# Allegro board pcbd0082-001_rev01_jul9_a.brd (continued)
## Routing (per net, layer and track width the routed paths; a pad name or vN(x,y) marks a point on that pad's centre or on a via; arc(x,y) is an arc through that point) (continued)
DDR0_32A_A12: length 67.2
  TOP w0.147: V3_A-A12.1 85.01,29.64 R218.1
  TOP w0.234: v2(66.9,44.28) U1.Y8
  03_SIG w0.121: V1_A-A12.1 84.62,51.73 84.62,40.96 V2_A-A12.1 84.62,40.17 84.62,29.41 V3_A-A12.1
  08_SIG w0.121: V1_A-A12.1 85.01,51.88 85.41,51.49 85.41,50.11
  08_SIG w0.189: v2(66.9,44.28) 68.4,42.78 74.12,42.78 74.37,43.04 75.09,43.04 75.1,43.02 76.52,43.02 76.54,43.04 78.33,43.04 78.75,42.62 78.75,42.37 78.93,42.19 87.73,42.19 87.75,42.2 88.75,42.2 88.94,42.39 88.94,49.27 88.73,49.48 86.83,49.48 86.68,49.33 86.68,47.67 86.5,47.5 85.64,47.5 85.41,47.73 85.41,50.11
  BOTTOM w0.147: U17.N7 V1_A-A12.1 ; U18.N7 V2_A-A12.1 ; U19.N7 V3_A-A12.1
DDR0_32A_A13: length 67.3
  TOP w0.147: V3_A-A13.1 87.41,32.65 R219.1
  TOP w0.234: v2(66.9,49.28) U1.AE8
  07_SIG w0.121: V3_A-A13.1 87.87,33.46 87.87,44.12 V2_A-A13.1 87.81,44.96 87.81,55.73 V1_A-A13.1
  07_SIG w0.189: V1_A-A13.1 87.85,56.56 87.85,60.42 87.84,60.43 87.84,60.68 87.66,60.86 65.95,60.86 65.75,60.65 65.75,59.23 66,58.98 67.11,58.98 67.32,58.77 67.32,57.14 67.33,57.13 67.33,56.47 67.34,56.46 67.34,56.1 67.33,56.1 67.33,56.06 66.4,55.13 66.4,49.78 v2(66.9,49.28)
  BOTTOM w0.147: U18.T3 V2_A-A13.1 ; U17.T3 V1_A-A13.1 ; U19.T3 V3_A-A13.1
DDR0_32A_A14: length 67.3
  TOP w0.147: V3_A-A14.1 87.41,29.37 R220.1
  TOP w0.234: v8(67.9,38.28) U1.R7
  04_SIG w0.121: V3_A-A14.1 87.87,29.46 87.87,40.12 V2_A-A14.1 87.87,41.03 87.87,51.67 V1_A-A14.1
  08_SIG w0.189: v8(67.9,38.28) 68.39,37.8 70.14,37.8 70.63,38.28 74.81,38.28 74.98,38.46 74.98,41.55 75.17,41.73 75.17,41.75 75.35,41.93 77.23,41.93 77.51,41.65 77.51,41.25 77.71,41.04 87.72,41.04 87.75,41.02 89.44,41.02 89.45,41.03 89.74,41.03 89.75,41.04 89.93,41.04 90.11,41.22 90.11,41.69 90.13,41.71 90.13,51.2 90.11,51.22 90.11,51.95 89.93,52.13 V1_A-A14.1
  BOTTOM w0.147: U17.T7 V1_A-A14.1 ; U18.T7 V2_A-A14.1 ; U19.T7 V3_A-A14.1
DDR0_32A_BA0: length 68.5
  TOP w0.147: R224.1 83.43,34.6 V3_A-BA0.1
  TOP w0.234: v8(65.9,41.28) U1.U9
  03_SIG w0.121: 84.61,57.97 84.61,57.32 V1_A-BA0.1
  03_SIG w0.189: 84.61,57.97 84.61,60.18 84.61,60.19 84.61,60.2 83.9,60.91 77,60.91 77,60.9 70,60.9 69.99,60.89 69.91,60.89 66.95,57.93 66.95,57.36 66.4,56.81 66.4,50.05 66.13,49.78 65.75,49.78 65.4,49.43 65.4,41.78 v8(65.9,41.28)
  07_SIG w0.121: V3_A-BA0.1 83.82,34.21 83.82,44.97 V2_A-BA0.1 83.82,45.76 83.82,56.42 84.21,56.82 V1_A-BA0.1
  BOTTOM w0.147: U17.M2 V1_A-BA0.1 ; U18.M2 V2_A-BA0.1 ; U19.M2 V3_A-BA0.1
DDR0_32A_BA1: length 68.5
  TOP w0.147: V3_A-BA1.1 84.19,29.04 R223.1
  TOP w0.234: v8(68.9,46.28) U1.AB6
  03_SIG w0.121: V1_A-BA1.1 85.41,50.93 85.41,40.17 V2_A-BA1.1 85.41,39.37 85.41,28.61 V3_A-BA1.1
  08_SIG w0.189: V1_A-BA1.1 84.59,51.75 84.59,51.94 84.58,51.95 84.58,52.3 84.84,52.55 84.84,52.55 86.03,53.74 87.7,53.74 87.75,53.79 88.58,53.79 88.86,54.07 88.86,54.33 88.68,54.51 85.69,54.51 85.56,54.38 85.56,53.85 85.33,53.62 85.08,53.62 84.9,53.79 84.9,54 84.75,54.15 84.34,54.15 84.16,53.97 84.16,52.78 83.96,52.58 83.71,52.58 83.5,52.78 83.5,53.97 83.32,54.15 82.94,54.15 82.79,54 82.79,53.47 82.66,53.34 82.33,53.34 82.18,53.49 82.18,53.97 82,54.15 81.67,54.15 81.52,54 81.52,53.54 81.34,53.36 78.73,53.36 78.15,52.78 77.78,52.78 77.2,53.36 77.2,53.36 75.17,53.36 74.72,52.92 74.72,49.84 74.73,49.84 74.73,49.42 74.74,49.41 74.74,48.95 74.66,48.87 74.66,47.97 74.47,47.78 72.58,47.78 72.4,47.61 72.4,46.99 72.13,46.72 71.63,46.72 71.36,46.99 71.36,47.58 71.16,47.78 70.61,47.78 70.4,47.58 70.4,46.86 70.3,46.76 69.09,46.76 68.9,46.57 v8(68.9,46.28)
  BOTTOM w0.147: U19.N8 V3_A-BA1.1 ; U17.N8 V1_A-BA1.1 ; U18.N8 V2_A-BA1.1
DDR0_32A_BA2: length 67.9
  TOP w0.147: R222.1 84.21,32.34 V3_A-BA2.1
  TOP w0.234: v8(68.9,48.28) U1.AD6
  04_SIG w0.121: V1_A-BA2.1 83.82,55.73 83.82,44.96 V2_A-BA2.1 83.82,44.17 83.82,33.41 V3_A-BA2.1
  07_SIG w0.121: V1_A-BA2.1 84.21,56.37 84.61,56.76 84.61,58.02
  07_SIG w0.189: v8(68.9,48.28) 68.9,47.96 69.09,47.78 69.78,47.78 69.85,47.85 70.08,47.85 70.34,48.1 70.34,49.46 69.96,49.84 69.96,50.73 70.34,51.1 70.34,51.46 69.96,51.84 69.96,52.73 70.34,53.1 70.34,54.46 69.33,55.47 69.33,55.9 70.04,56.62 70.04,58.04 69.91,58.17 69.58,58.17 69.45,58.04 69.45,56.84 69.33,56.72 69.02,56.72 68.85,56.89 68.85,58.65 68.84,58.67 68.84,59.24 68.85,59.25 68.85,59.46 69.04,59.65 86.15,59.65 86.34,59.47 86.34,59.2 86.09,58.95 84.86,58.95 84.61,58.7 84.61,58.02
  BOTTOM w0.147: U19.M3 V3_A-BA2.1 ; U18.M3 V2_A-BA2.1 ; U17.M3 V1_A-BA2.1
DDR0_32A_CAS_L: length 67.1
  TOP w0.147: V3_A-CAS.1 82.61,32.52 R226.1
  TOP w0.234: v2(65.9,46.28) U1.AB9
  03_SIG w0.121: 83.79,57.91 83.79,57.11 83.81,57.09 83.81,56.76 83.56,56.52 83.01,56.52 V1_A-CAS.1
  03_SIG w0.189: v2(65.9,46.28) 66.4,46.78 66.4,49.43 66.75,49.78 67.02,49.78 67.33,50.1 67.34,50.1 67.34,53.46 67.33,53.47 67.33,53.58 66.79,54.13 66.79,55.55 67.34,56.1 67.34,56.16 67.34,57.77 70.07,60.5 70.15,60.5 70.16,60.51 82.35,60.51 82.54,60.32 82.54,58.32 82.71,58.14 83.02,58.14 83.2,58.32 83.2,60.37 83.32,60.5 83.75,60.5 84.21,60.04 84.21,58.41 83.79,57.99 83.79,57.91
  04_SIG w0.121: V1_A-CAS.1 82.22,55.73 82.22,44.96 V2_A-CAS.1 82.22,44.17 82.22,33.41 V3_A-CAS.1
  BOTTOM w0.147: U19.K3 V3_A-CAS.1 ; U18.K3 V2_A-CAS.1 ; U17.K3 V1_A-CAS.1
DDR0_32A_CB0: length 19
  TOP w0.132: v8(72.9,41.28) U1.U2
  04_SIG w0.121: V_A-CB0.1 79.01,34.21 79.01,35.31 79.18,35.48 81.17,35.48 81.29,35.61 81.29,37.82 81.11,38 74.79,38 74.66,38.12 74.66,40.33 74.46,40.54 73.14,40.54 72.9,40.78 v8(72.9,41.28)
  BOTTOM w0.147: U19.F2 V_A-CB0.1
DDR0_32A_CB1: length 19
  TOP w0.132: v8(70.9,39.28) U1.T4
  04_SIG w0.121: V_A-CB1.1 80.21,30.47 80.05,30.63 73.85,30.63 72.58,31.9 72.58,35.3 71.62,36.27 71.62,38.5 70.9,39.22 v8(70.9,39.28)
  BOTTOM w0.147: U19.H7 V_A-CB1.1
DDR0_32A_CB2: length 19.1
  TOP w0.132: v2(70.9,41.28) U1.U4
  04_SIG w0.121: V_A-CB2.1 78.21,33.41 78.21,35.58 78.52,35.89 78.9,35.89 79.9,36.88 79.9,37.21 79.49,37.62 74.54,37.62 74.31,37.84 74.31,39.91 74.19,40.03 71.11,40.03 70.9,40.24 v2(70.9,41.28)
  BOTTOM w0.147: U19.E3 V_A-CB2.1
DDR0_32A_CB3: length 19.5
  TOP w0.132: v8(69.9,39.28) U1.T5
  04_SIG w0.121: v8(69.9,39.28) 71.31,37.87 71.31,36.01 72.3,35.02 72.3,31.72 73.7,30.33 78.7,30.33 79.81,29.21 79.81,28.61 V_A-CB3.1
  BOTTOM w0.147: U19.H8 V_A-CB3.1
DDR0_32A_CB4: length 19.1
  TOP w0.132: v8(68.9,39.28) U1.T6
  04_SIG w0.121: V_A-CB4.1 78.21,28.61 78.21,29.19 77.69,29.72 73.24,29.72 69.46,33.5 69.46,38.89 69.06,39.28 v8(68.9,39.28)
  BOTTOM w0.147: U19.F8 V_A-CB4.1
DDR0_32A_CB5: length 19.1
  TOP w0.132: v8(69.9,38.28) U1.R5
  04_SIG w0.121: V_A-CB5.1 78.61,29.83 78.42,30.02 73.49,30.02 70.48,33.03 70.48,33.66 70.6,33.78 71.39,33.78 71.51,33.9 71.51,34.78 71.39,34.9 70.6,34.9 70.48,35.02 70.48,38.11 70.31,38.28 v8(69.9,38.28)
  BOTTOM w0.147: U19.F7 V_A-CB5.1
DDR0_32A_CB6: length 19.3
  TOP w0.132: v2(73.9,41.28) U1.U1
  04_SIG w0.121: v2(73.9,41.28) 74.37,41.28 74.92,40.74 74.92,38.61 75.12,38.4 81.52,38.4 81.7,38.23 81.7,35.29 81.37,34.96 81.37,34.34 81.24,34.21 80.78,34.21 80.66,34.34 80.66,34.97 80.56,35.08 79.97,35.08 79.81,34.92 79.81,34.21 V_A-CB6.1
  BOTTOM w0.147: U19.G2 V_A-CB6.1
DDR0_32A_CB7: length 19.1
  TOP w0.132: v8(71.9,39.28) U1.T3
  04_SIG w0.121: V_A-CB7.1 80.25,32.97 80.25,31.03 80.13,30.91 73.98,30.91 72.86,32.03 72.86,35.56 72.4,36.02 72.4,39.16 72.28,39.28 v8(71.9,39.28)
  BOTTOM w0.147: U19.H3 V_A-CB7.1
DDR0_32A_CK0_N: length 72.1
  TOP w0.099: v3(82.61,29.01) 82.28,29.34 82.28,29.74 81.96,30.07 81.14,30.07 80.91,30.3 80.62,30.3 R8.1 ; C71.2 82.58,52.16 v3(82.61,52.13) ; v8(66.9,42.28) U1.V7
  03_SIG w0.096: v3(82.61,52.13) 82.21,51.72 82.21,51.16 81.9,50.86 81.9,50.32 81.39,49.81 81.39,44.35 82.34,43.4 82.34,40.84 v3(82.61,40.57) 82.22,40.18 82.22,39.58 81.9,39.27 81.9,38.89 81.39,38.38 81.39,32.03 82.34,31.08 82.34,29.28 v3(82.61,29.01)
  08_SIG w0.096: v8(66.9,42.28) 66.9,42.17 66.62,41.89 66.4,41.89 66.16,42.13 66.16,42.69 66.51,43.04 66.51,44.44 66.74,44.67 74.23,44.67 74.5,44.94 74.53,44.94 74.61,45.01 74.61,45.99 75.25,46.64 77.8,46.64 78.07,46.9 78.07,47.47 78.17,47.57 78.61,47.57 78.72,47.46 78.72,46.91 78.98,46.65 78.99,46.65 79.04,46.61 79.61,46.61 79.9,46.89 79.9,49.75 80,49.85 80.52,49.85 80.63,49.75 80.63,46.84 80.88,46.58 81.64,46.58 81.9,46.84 81.9,47.16 82.01,47.26 84.18,47.26 84.44,47.52 84.44,48.01 84.18,48.27 82.01,48.27 81.9,48.38 81.9,48.65 82.01,48.76 82.91,48.76 83.17,49.02 83.17,49.51 82.91,49.77 82.01,49.77 81.9,49.87 81.9,50.86 82.22,51.18 82.22,51.49 82.32,51.59 82.32,51.6 82.61,51.89 v3(82.61,52.13)
  BOTTOM w0.099: U18.K7 v3(82.61,40.57) ; U17.K7 v3(82.61,52.13) ; U19.K7 v3(82.61,29.01)
DDR0_32A_CK0_P: length 71.8
  TOP w0.099: v3(81.81,29.01) 82.05,29.25 82.05,29.64 81.86,29.83 81.04,29.83 80.81,30.07 80.62,30.07 R7.1 ; v3(81.81,52.13) 81.74,52.2 C71.1 ; v8(66.9,41.28) U1.V8
  03_SIG w0.096: v3(81.81,29.01) 82.08,29.28 82.08,30.97 81.13,31.92 81.13,38.49 81.64,38.99 81.64,39.38 81.42,39.61 81.42,40.18 v3(81.81,40.57) 82.08,40.84 82.08,43.29 81.13,44.24 81.13,49.92 81.64,50.42 81.64,50.94 81.42,51.16 81.42,51.73 v3(81.81,52.13)
  08_SIG w0.096: v3(81.81,52.13) 81.81,51.88 81.42,51.49 81.42,51.16 81.53,51.05 81.53,51.04 81.64,50.93 81.64,49.77 81.9,49.51 82.81,49.51 82.91,49.4 82.91,49.13 82.81,49.02 81.9,49.02 81.64,48.76 81.64,48.27 81.9,48.01 84.08,48.01 84.18,47.9 84.18,47.63 84.08,47.52 81.9,47.52 81.64,47.26 81.64,46.95 81.54,46.84 81.02,46.84 80.91,46.95 80.91,49.83 80.63,50.11 79.89,50.11 79.64,49.85 79.64,47 79.55,46.91 79.09,46.91 78.98,47.02 78.98,47.57 78.71,47.83 78.07,47.83 77.81,47.57 77.81,47.01 77.71,46.91 75.16,46.91 74.38,46.14 74.38,45.16 74.35,45.12 74.35,45.09 74.15,44.89 66.65,44.89 66.29,44.53 66.29,43.13 65.94,42.78 65.94,42.04 66.31,41.68 66.51,41.68 v8(66.9,41.28)
  BOTTOM w0.099: U18.J7 v3(81.81,40.57) ; U19.J7 v3(81.81,29.01) ; U17.J7 v3(81.81,52.13)
DDR0_32A_CKE0: length 67.1
  TOP w0.139: 82.54,27.34 82.41,27.21 R231.1
  TOP w0.147: 82.54,27.34 v3(82.61,27.41)
  TOP w0.234: v2(67.9,47.28) U1.AC7
  03_SIG w0.121: v10(82.61,50.53) 83.01,50.13 83.01,39.37 v3(82.61,38.97) 83.01,38.57 83.01,27.81 v3(82.61,27.41)
  08_SIG w0.121: v10(82.61,50.53) 83.01,50.92 83.01,52.44 ; 78.25,52.47 78.22,52.44 78.22,50.32
  08_SIG w0.189: 83.01,52.44 83.01,52.78 82.83,52.96 81.39,52.96 81.22,52.78 81.22,51.94 81.06,51.79 80.78,51.79 80.66,51.92 80.66,52.32 80.42,52.55 78.37,52.55 78.28,52.47 78.25,52.47 ; 78.22,50.32 77.97,50.06 75.3,50.06 75.12,49.88 75.12,49.58 75.28,49.42 78.54,49.42 78.7,49.25 78.7,48.97 78.58,48.86 75.26,48.86 75.12,48.72 75.12,48.31 75.22,48.21 77.2,48.21 77.28,48.13 77.28,47.73 77.15,47.6 75.17,47.6 74.36,46.78 73.57,46.78 73.39,46.61 73.39,46.05 73.22,45.87 73.11,45.87 73.08,45.85 66.72,45.85 66.69,45.87 66.51,45.87 66.34,46.04 66.34,46.56 66.51,46.73 67.78,46.73 67.95,46.91 67.95,47.23 v2(67.9,47.28)
  BOTTOM w0.147: U17.K9 v10(82.61,50.53) ; U18.K9 v3(82.61,38.97) ; U19.K9 v3(82.61,27.41)
DDR0_32A_CS0_L: length 68.7
  TOP w0.147: v3(83.41,33.81) 82.54,34.69 R229.1
  TOP w0.234: v2(65.9,43.28) U1.W9
  03_SIG w0.189: v2(65.9,43.28) 66.26,42.92 66.97,42.92 67.4,43.36 67.4,49.4 67.96,49.97 67.96,50.7 68.31,51.05 68.31,51.08 68.34,51.1 68.34,51.46 68.31,51.49 68.31,52.35 67.81,52.86 67.81,53.74 67.55,54 67.55,54.01 67.46,54.1 67.46,55.46 67.73,55.72 67.73,57.6 70.23,60.11 70.31,60.11 70.32,60.12 78.35,60.12 78.52,59.95 78.52,59.75 78.68,59.59 78.92,59.59 79.09,59.75 79.09,59.95 79.25,60.12 79.57,60.12 79.74,59.95 79.74,59.12 79.9,58.95 80.14,58.95 80.31,59.12 80.31,59.95 80.47,60.12 80.71,60.12 80.88,59.95 80.88,59.12 81.04,58.95 81.28,58.95 81.44,59.12 81.44,59.95 81.61,60.12 81.93,60.12 82.09,59.96 82.09,58.25 v3(83.41,56.93)
  07_SIG w0.121: v3(83.41,56.93) 83.02,56.53 83.02,45.76 v10(83.41,45.37) 83.02,44.97 83.02,34.21 v3(83.41,33.81)
  BOTTOM w0.147: U17.L2 v3(83.41,56.93) ; U18.L2 v10(83.41,45.37) ; U19.L2 v3(83.41,33.81)
DDR0_32A_DM0: length 15.6
  TOP w0.132: v2(73.9,52.28) U1.AH1
  04_SIG w0.121: v2(73.9,52.28) 73.9,52.68 74.55,53.33 77.37,53.33 77.54,53.15 77.54,53.06 77.79,52.81 78.14,52.81 78.66,53.33 79.32,53.33 79.62,53.62 79.96,53.62 80.25,53.33 81.61,53.33 81.7,53.24 81.7,52.86 81.57,52.73 78.85,52.73 78.65,52.53 77.63,52.53 77.57,52.46 77.57,52.37 V_A-DM0.1
  BOTTOM w0.147: U17.E7 V_A-DM0.1
DDR0_32A_DM1: length 14.4
  TOP w0.132: v8(71.9,48.28) U1.AD3
  03_SIG w0.121: V_A-DM1.1 76.61,55.73 76.61,55.16 76.37,54.91 75.11,54.91 74.07,53.87 73.73,53.87 73.72,53.88 72.73,53.88 72.71,53.9 72.68,53.9 72.32,54.26 72.06,54.26 71.92,54.13 71.92,53.83 72.5,53.26 72.5,48.5 72.27,48.28 v8(71.9,48.28)
  BOTTOM w0.147: U17.D3 V_A-DM1.1
DDR0_32A_DM2: length 12.8
  TOP w0.132: v2(69.9,44.28) U1.Y5
  04_SIG w0.105: v2(69.9,44.28) 70.05,44.28 70.65,43.68 72.15,43.68 72.5,43.33 72.5,43.12 72.74,42.89 73.07,42.89 73.5,42.46 73.5,42.12 73.74,41.89 74.28,41.89
  04_SIG w0.121: V_A-DM2.1 77.81,41.15 77.02,41.94 76.8,41.94 76.61,41.76 76.61,41.2 76.38,40.97 76.03,40.97 75.81,41.19 75.81,41.53 75.53,41.81 75.29,41.81 75.16,41.68 74.79,41.68 74.58,41.89 74.28,41.89
  BOTTOM w0.254: U18.E7 V_A-DM2.1
DDR0_32A_DM3: length 10.9
  TOP w0.132: v2(69.9,42.28) U1.V5
  03_SIG w0.105: v2(69.9,42.28) 69.5,43.2 69.5,43.45 69.74,43.68 69.96,43.68 69.98,43.68 70.15,43.68 70.43,43.81 70.65,43.88 70.84,43.88 70.85,43.89 71.06,43.89 71.3,44.12 71.3,44.53 71.65,44.89 74.28,44.89
  03_SIG w0.121: V_A-DM3.1 76.32,44.97 75.3,44.97 74.31,44.89 74.28,44.89
  BOTTOM w0.254: U18.D3 V_A-DM3.1
DDR0_32A_DM4: length 19.1
  TOP w0.132: v8(68.9,38.28) U1.R6
  04_SIG w0.121: V_A-DM4.1 77.41,29.41 72.33,29.41 72,29.74 69.51,29.74 68.44,30.81 68.44,34.79 68.9,35.25 v8(68.9,38.28)
  BOTTOM w0.147: U19.E7 V_A-DM4.1
DDR0_32A_DQ0: length 15.7
  TOP w0.132: v8(69.9,49.28) U1.AE5
  04_SIG w0.105: v8(69.9,49.28) 69.9,49.36 70.3,49.76 70.3,53.53 70.65,53.89 71.06,53.89 73.7,56.53
  04_SIG w0.121: V_A-DQ00.1 78.47,56.93 78.07,57.33 74.5,57.33 73.7,56.53
  BOTTOM w0.147: U17.F2 V_A-DQ00.1
DDR0_32A_DQ1: length 15.5
  TOP w0.132: v8(71.9,49.28) U1.AE3
  04_SIG w0.105: v8(71.9,49.28) 71.3,49.88 71.3,53.53 72.65,54.88 74.14,54.88 74.18,54.93 74.22,54.93
  04_SIG w0.121: 74.22,54.93 74.38,54.93 74.43,54.88 76.34,54.88 76.61,55.16 76.61,55.49 76.85,55.73 77.98,55.73 78.19,55.94 78.19,55.96 78.76,56.53 78.78,56.53 78.98,56.73 79.06,56.73 79.11,56.77 79.26,56.77 V_A-DQ01.1
  BOTTOM w0.147: U17.G2 V_A-DQ01.1
DDR0_32A_DQ2: length 15.8
  TOP w0.132: v8(72.9,49.28) U1.AE2
  04_SIG w0.121: V_A-DQ02.1 80.79,51.33 80.99,51.13 80.99,50.82 81.27,50.54 81.27,48.31 81.09,48.13 80.84,48.13 80.35,48.61 80.07,48.61 79.59,48.13 74.82,48.13 74.81,48.13 74.49,48.13 74.38,48.23 74.38,48.61 74.21,48.79 72.5,48.79 72.38,48.92 72.38,49.16 72.5,49.28 v8(72.9,49.28)
  BOTTOM w0.147: U17.H8 V_A-DQ02.1
DDR0_32A_DQ3: length 15.8
  TOP w0.132: v2(73.9,48.28) U1.AD1
  04_SIG w0.121: v2(73.9,48.28) 73.52,48.28 73.39,48.16 73.39,47.9 73.49,47.8 81.55,47.8 81.7,47.95 81.7,50.72 81.32,51.1 81.32,51.94 81.13,52.13 V_A-DQ03.1
  BOTTOM w0.147: U17.H7 V_A-DQ03.1
DDR0_32A_DQ4: length 15.6
  TOP w0.132: v8(72.9,50.28) U1.AF2
  04_SIG w0.105: 74.28,54.68 72.74,54.68 71.5,53.45 71.5,51.12 71.74,50.89 71.91,50.89 72.51,50.28 v8(72.9,50.28)
  04_SIG w0.121: V_A-DQ04.1 79.81,56.53 79.21,56.53 78.96,56.28 78.86,56.28 78.44,55.85 78.44,55.83 78.08,55.48 77.67,55.48 77.41,55.22 77.41,55.16 77.18,54.93 77.11,54.93 76.82,54.64 74.32,54.64 74.28,54.68
  BOTTOM w0.147: U17.H3 V_A-DQ04.1
DDR0_32A_DQ5: length 15.2
  TOP w0.132: v8(70.9,49.28) U1.AE4
  04_SIG w0.105: v8(70.9,49.28) 70.61,49.28 70.5,49.39 70.5,51.08 70.73,51.3 70.73,51.84 70.5,52.06 70.5,53.45 70.74,53.68 71.15,53.68 72.56,55.09 72.83,55.09 73.47,55.73 74.28,55.73
  04_SIG w0.121: V_A-DQ05.1 77.81,56.41 77.69,56.53 74.52,56.53 74.43,56.44 74.43,55.88 74.28,55.73
  BOTTOM w0.147: U17.E3 V_A-DQ05.1
DDR0_32A_DQ6: length 15.4
  TOP w0.132: v2(72.9,51.28) U1.AG2
  04_SIG w0.121: v2(72.9,51.28) 72.9,51.35 73.27,51.71 74.69,51.71 74.89,51.51 74.89,49.05 75.16,48.78 79.09,48.78 79.72,49.41 79.72,49.9 79.56,50.06 78.44,50.06 78.21,50.29 78.21,51.73 V_A-DQ06.1
  BOTTOM w0.147: U17.F7 V_A-DQ06.1
DDR0_32A_DQ7: length 15.1
  TOP w0.132: v2(73.9,51.28) U1.AG1
  04_SIG w0.121: v2(73.9,51.28) 74.28,51.28 74.43,51.13 74.43,49.05 74.76,48.72 74.76,48.56 74.87,48.46 79.46,48.46 79.95,48.94 80.81,48.94 80.94,49.07 80.94,50.47 80.48,50.93 79.01,50.93 V_A-DQ07.1
  BOTTOM w0.147: U17.F8 V_A-DQ07.1
DDR0_32A_DQ8: length 14.3
  TOP w0.132: v2(71.9,46.28) U1.AB3
  03_SIG w0.105: 74.28,46.11 74.07,45.89 74.01,45.89 74,45.89 72.36,45.89 71.97,46.28 v2(71.9,46.28)
  03_SIG w0.121: V_A-DQ08.1 77.04,52.13 77.41,51.76 77.41,50.19 77.52,50.09 78.07,50.09 78.27,49.88 78.27,46.84 78.07,46.63 75.3,46.63 75,46.34 74.51,46.34 74.28,46.11
  BOTTOM w0.147: U17.D7 V_A-DQ08.1
DDR0_32A_DQ9: length 13.8
  TOP w0.132: v8(72.9,48.28) U1.AD2
  03_SIG w0.121: v8(72.9,48.28) 73.21,48.28 73.39,48.46 73.39,51.46 73.15,51.71 73.15,51.96 73.39,52.21 73.39,52.76 73.51,52.88 74.07,52.88 74.3,53.12 74.3,53.13 74.41,53.24 74.41,53.72 74.56,53.87 74.87,53.87 74.97,53.97 74.97,54.25 75.09,54.38 75.43,54.38 75.53,54.28 75.53,54 75.65,53.87 75.91,53.87 76.03,54 76.03,54.41 76.14,54.51 76.39,54.51 76.49,54.41 76.49,54 76.62,53.87 76.89,53.87 77.01,53.99 77.01,55.33 V_A-DQ09.1
  BOTTOM w0.147: U17.C3 V_A-DQ09.1
DDR0_32A_DQ10: length 14.4
  TOP w0.132: v2(70.9,46.28) U1.AB4
  03_SIG w0.105: v2(70.9,46.28) 70.9,46.55 71.03,46.68 74.12,46.68 74.18,46.62 74.28,46.62
  03_SIG w0.121: V_A-DQ10.1 76.21,51.09 76.61,50.69 76.61,49.94 76.77,49.78 77.84,49.78 77.94,49.68 77.94,47.12 77.71,46.89 75.09,46.89 74.82,46.62 74.62,46.62 74.28,46.62
  BOTTOM w0.147: U17.C8 V_A-DQ10.1
DDR0_32A_DQ11: length 13.8
  TOP w0.132: v2(73.9,47.28) U1.AC1
  03_SIG w0.121: V_A-DQ11.1 75.13,52.13 75.01,52.01 75.01,49.71 75.17,49.55 75.37,49.55 75.63,49.81 75.86,49.81 75.99,49.67 75.99,49.24 76.11,49.12 77.15,49.12 77.23,49.03 77.23,48.65 77.12,48.54 76.4,48.54 76.3,48.44 76.3,48.39 76.3,48.17 76.42,48.06 77.13,48.06 77.23,47.95 77.23,47.58 77.15,47.49 76.47,47.49 76.23,47.74 76.06,47.74 75.81,47.49 74.89,47.49 74.7,47.3 74.54,47.14 74.18,47.14 74.04,47.28 v2(73.9,47.28)
  BOTTOM w0.147: U17.B8 V_A-DQ11.1
DDR0_32A_DQ12: length 13.9
  TOP w0.132: v2(69.9,47.28) U1.AC5
  03_SIG w0.105: v2(69.9,47.28) 69.9,47.72 70.5,48.33 70.5,48.45 70.94,48.89 71.06,48.89 71.3,49.12 71.3,54.49 71.67,54.86 72.07,54.86 72.73,55.52 73.19,55.52 73.8,56.13 74.28,56.13
  03_SIG w0.121: V_A-DQ12.1 75.41,56.13 74.28,56.13
  BOTTOM w0.147: U17.A2 V_A-DQ12.1
DDR0_32A_DQ13: length 14.3
  TOP w0.132: v8(72.9,47.28) U1.AC2
  03_SIG w0.105: 74.28,46.86 74.22,46.86 74.2,46.88 73.65,46.88 73.25,47.28 v8(72.9,47.28)
  03_SIG w0.121: V_A-DQ13.1 75.85,52.49 76.2,52.49 76.34,52.35 76.34,51.99 76.19,51.84 75.94,51.84 75.81,51.71 75.81,50.18 75.91,50.09 76.21,50.09 76.31,49.99 76.31,49.55 76.42,49.45 77.46,49.45 77.56,49.35 77.56,47.34 77.38,47.17 75.02,47.17 74.72,46.86 74.28,46.86
  BOTTOM w0.147: U17.A7 V_A-DQ13.1
DDR0_32A_DQ14: length 13.9
  TOP w0.132: v8(70.9,48.28) U1.AD4
  03_SIG w0.105: 73.72,54.68 73.09,55.32 72.82,55.32 72.16,54.66 71.76,54.66 71.5,54.4 71.5,48.39 71.27,48.16 71.03,48.16 v8(70.9,48.28)
  03_SIG w0.121: V_A-DQ14.1 75.41,55.56 75.15,55.83 74.43,55.83 74.31,55.71 74.31,54.84 74.16,54.69 73.73,54.69 73.72,54.68
  BOTTOM w0.147: U17.A3 V_A-DQ14.1
DDR0_32A_DQ15: length 14.4
  TOP w0.132: v8(69.9,48.28) U1.AD5
  03_SIG w0.121: V_A-DQ15.1 76.19,56.93 75.58,56.53 73.71,56.53 73.3,56.12 73.3,56.12 73.07,55.88 73.06,55.88 72.96,55.78 71.82,55.78 71.3,55.26 71.3,55.08 70.91,54.69 70.73,54.69 70.5,54.45 70.5,49.6 v8(69.9,48.28)
  BOTTOM w0.147: U17.C2 V_A-DQ15.1
DDR0_32A_DQ16: length 12.7
  TOP w0.132: v2(71.9,45.28) U1.AA3
  04_SIG w0.105: v2(71.9,45.28) 72.34,45.28 72.74,45.68 74.28,45.68
  04_SIG w0.121: 74.28,45.68 74.47,45.68 74.61,45.82 74.61,46.27 75.13,46.79 75.69,46.79 75.81,46.67 75.81,45.94 75.98,45.77 76.49,45.77 76.61,45.89 76.61,46.67 76.73,46.79 77.04,46.79 77.2,46.63 77.55,46.63 77.71,46.79 78.09,46.79 78.21,46.66 78.21,45.18 77.81,44.78 V_A-DQ16.1
  BOTTOM w0.254: U18.E3 V_A-DQ16.1
DDR0_32A_DQ17: length 12.7
  TOP w0.132: v2(73.9,46.28) U1.AB1
  04_SIG w0.121: v2(73.9,46.28) 73.9,46.71 74.49,47.3 81.11,47.3 81.29,47.12 81.29,45.92 81.14,45.77 80.05,45.77 79.65,45.37 V_A-DQ17.1
  BOTTOM w0.254: U18.G2 V_A-DQ17.1
DDR0_32A_DQ18: length 13.5
  TOP w0.132: v8(68.9,45.28) U1.AA6
  04_SIG w0.105: 74.28,42.64 74.18,42.64 74.14,42.68 73.65,42.68 73.3,43.03 73.3,43.43 73.29,43.43 73.29,43.45 72.85,43.89 70.74,43.89 70.5,44.12 70.5,44.24 69.96,44.78 v8(68.9,45.28)
  04_SIG w0.121: V_A-DQ18.1 78.61,41.18 78.3,41.5 77.84,41.5 77.15,42.19 74.79,42.19 74.34,42.64 74.28,42.64
  BOTTOM w0.254: U18.F7 V_A-DQ18.1
DDR0_32A_DQ19: length 13
  TOP w0.132: v2(73.9,45.28) U1.AA1
  04_SIG w0.121: V_A-DQ19.1 79.81,44.97 79.39,44.97 78.38,44.97 78.22,44.8 78.22,44.3 77.94,44.02 77.53,44.02 77.41,44.14 77.41,44.4 77.41,44.4 77.41,45.53 77.18,45.77 76.85,45.77 76.61,45.53 76.61,44.32 76.47,44.17 75.93,44.17 75.81,44.29 75.81,45.53 75.58,45.77 75.07,45.77 74.58,45.28 v2(73.9,45.28)
  BOTTOM w0.254: U18.H3 V_A-DQ19.1
DDR0_32A_DQ20: length 12.9
  TOP w0.132: v8(68.9,44.28) U1.Y6
  04_SIG w0.105: v8(68.9,44.28) 70.06,43.68 70.29,43.45 70.29,43.33 70.94,42.68 72.06,42.68 72.29,42.45 72.29,42.33 72.94,41.68 74.14,41.68 74.18,41.64 74.28,41.64
  04_SIG w0.121: V_A-DQ20.1 78.21,40.17 76.38,40.17 75.81,40.73 75.81,40.73 75.58,40.97 75.12,40.97 74.45,41.64 74.28,41.64
  BOTTOM w0.254: U18.F8 V_A-DQ20.1
DDR0_32A_DQ21: length 13.4
  TOP w0.132: v2(70.9,45.28) U1.AA4
  04_SIG w0.105: 74.12,45.92 74.08,45.88 72.65,45.88 72.44,45.68 71.74,45.68 71.34,45.28 v2(70.9,45.28)
  04_SIG w0.121: V_A-DQ21.1 79.01,45.77 79.58,45.77 79.81,46 79.81,46.77 79.54,47.04 74.94,47.04 74.31,46.41 74.31,46.11 74.12,45.92
  BOTTOM w0.254: U18.F2 V_A-DQ21.1
DDR0_32A_DQ22: length 13.5
  TOP w0.132: v2(72.9,44.28) U1.Y2
  04_SIG w0.105: v2(72.9,44.28) 73.2,44.28 73.5,43.98 73.5,43.12 73.74,42.89 74.28,42.89
  04_SIG w0.121: V_A-DQ22.1 79.81,40.17 79.81,40.77 80.09,41.04 80.58,41.04 80.78,41.25 80.78,41.63 80.64,41.77 78,41.77 77.32,42.46 74.94,42.46 74.51,42.89 74.28,42.89
  BOTTOM w0.254: U18.H8 V_A-DQ22.1
DDR0_32A_DQ23: length 12.6
  TOP w0.132: v2(73.9,44.28) U1.Y1
  04_SIG w0.121: V_A-DQ23.1 81.27,40.57 81.43,40.73 81.43,41.9 81.25,42.07 78.05,42.07 77.42,42.7 75.05,42.7 74.41,43.34 74.41,43.97 74.09,44.28 v2(73.9,44.28)
  BOTTOM w0.254: U18.H7 V_A-DQ23.1
DDR0_32A_DQ24: length 9.9
  TOP w0.132: v8(69.9,43.28) U1.W5
  03_SIG w0.105: 74.28,44.47 74.27,44.47 74.06,44.68 73.74,44.68 73.47,44.42 73.33,44.42 73.06,44.68 72.74,44.68 72.47,44.42 72.33,44.42 72.06,44.68 71.74,44.68 71.5,44.45 71.5,44.04 71.14,43.68 70.74,43.68 70.5,43.45 70.5,43.12 70.73,42.9 70.73,42.67 70.65,42.59 70.19,42.59 69.96,42.82 69.96,42.95
  03_SIG w0.121: v8(69.9,43.28) 69.9,43.01 69.96,42.95 ; V_A-DQ24.1 75.26,44.42 75.07,44.42 74.88,44.22 74.63,44.22 74.38,44.47 74.28,44.47
  BOTTOM w0.147: U18.A2 V_A-DQ24.1
DDR0_32A_DQ25: length 10.2
  TOP w0.132: v2(69.9,41.28) U1.U5
  03_SIG w0.121: v2(69.9,41.28) 69.9,40.35 70.35,39.9 70.6,39.9 70.81,39.69 71.07,39.69 71.3,39.45 71.3,39.2 71.93,38.57 75.58,38.57 75.81,38.8 75.81,39.13 76.06,39.38 76.06,39.62 V_A-DQ25.1
  BOTTOM w0.254: U18.C8 V_A-DQ25.1
DDR0_32A_DQ26: length 10.4
  TOP w0.132: v8(72.9,42.28) U1.V2
  03_SIG w0.121: V_A-DQ26.1 75.37,41.37 75.01,41.01 75.01,40.38 74.79,40.16 74.54,40.16 74.41,40.28 74.41,40.54 74.28,40.66 74.03,40.66 73.9,40.54 73.9,39.9 73.77,39.77 73.54,39.77 73.42,39.9 73.42,40.54 73.3,40.66 73.04,40.66 72.92,40.54 72.92,39.9 72.8,39.77 72.63,39.77 72.38,40.03 72.38,41.76 v8(72.9,42.28)
  BOTTOM w0.147: U18.A7 V_A-DQ26.1
DDR0_32A_DQ27: length 10
  TOP w0.132: v2(73.9,42.28) U1.V1
  03_SIG w0.121: v2(73.9,42.28) 73.9,41.93 74.02,41.81 75.69,41.81 75.81,41.69 75.81,40.28 75.92,40.17 76.38,40.17 76.61,39.93 76.61,39.6 76.85,39.37 78.09,39.37 78.21,39.49 78.21,40.05 78.09,40.17 77.41,40.17 V_A-DQ27.1
  BOTTOM w0.254: U18.D7 V_A-DQ27.1
DDR0_32A_DQ28: length 10.1
  TOP w0.132: v2(70.9,42.28) U1.V4
  03_SIG w0.121: v2(70.9,42.28) 70.9,41.85 71.3,41.45 71.3,41.12 70.98,40.79 70.98,40.16 71.45,39.69 72.07,39.69 72.3,39.45 72.3,38.99 72.42,38.87 74.39,38.87 75.01,39.49 75.01,39.93 75.25,40.17 75.29,40.17 75.41,40.29 V_A-DQ28.1
  BOTTOM w0.147: U18.B8 V_A-DQ28.1
DDR0_32A_DQ29: length 9.9
  TOP w0.132: v8(71.9,43.28) U1.W3
  03_SIG w0.105: v8(71.9,43.28) 71.69,43.28 71.43,43.02 71.43,41.99 71.53,41.89 72.06,41.89 72.5,42.33 72.5,42.45 72.76,42.7 72.76,42.86 72.5,43.12 72.5,43.45 72.74,43.68 74.06,43.68 74.15,43.59 74.28,43.59
  03_SIG w0.121: 74.28,43.59 74.4,43.59 75.17,42.82 75.43,42.82 75.55,42.94 75.55,43.65 75.43,43.77 V_A-DQ29.1
  BOTTOM w0.147: U18.A3 V_A-DQ29.1
DDR0_32A_DQ30: length 10
  TOP w0.132: v2(70.9,43.28) U1.W4
  03_SIG w0.105: v2(70.9,43.28) 71.31,43.28 71.71,43.68 72.44,43.68 72.65,43.88 74.24,43.88 74.28,43.84
  03_SIG w0.121: 74.28,43.84 74.85,43.84 75.18,44.17 75.58,44.17 75.81,43.93 75.81,43.6 76.05,43.37 76.73,43.37 77.15,43.78 77.15,43.95 76.93,44.17 76.85,44.17 76.45,44.57 V_A-DQ30.1
  BOTTOM w0.254: U18.C3 V_A-DQ30.1
DDR0_32A_DQ31: length 10
  TOP w0.132: v8(68.9,43.28) U1.W6
  03_SIG w0.105: 74.09,45.68 71.74,45.68 71.5,45.45 71.5,45.38 71.49,45.36 71.49,45.11 71.31,44.93 71.11,44.93 71.06,44.89 70.94,44.89 70.5,44.45 70.5,44.33 70.06,43.89 69.5,43.89 v8(68.9,43.28)
  03_SIG w0.121: V_A-DQ31.1 76.19,45.37 75.79,45.77 75.25,45.77 75.16,45.68 74.09,45.68
  BOTTOM w0.254: U18.C2 V_A-DQ31.1
DDR0_32A_DQS0_N: length 15.7
  TOP w0.099: v2(73.9,49.28) U1.AE1
  04_SIG w0.096: V_A-DQS0-N.1 78.91,55.83 78.44,55.36 78.44,54.6 78.75,54.3 78.75,54.13 78.62,54 77.6,54 77.47,53.87 74.29,53.87 74.27,53.89 72.65,53.89 72.29,53.53 72.29,51.03 72.65,50.67 73.06,50.67 73.29,50.44 73.29,50.03 73.9,49.42 v2(73.9,49.28)
  BOTTOM w0.099: U17.G3 V_A-DQS0-N.1
DDR0_32A_DQS0_P: length 15.5
  TOP w0.099: v2(73.9,50.28) U1.AF1
  04_SIG w0.096: V_A-DQS0-P.1 79.41,55.46 79.31,55.57 79.02,55.57 78.7,55.26 78.7,54.71 79.01,54.41 79.01,54.02 78.73,53.74 77.7,53.74 77.62,53.66 74.2,53.66 74.18,53.67 72.74,53.67 72.51,53.44 72.51,51.12 72.74,50.89 73.15,50.89 73.5,50.53 73.5,50.12 73.82,49.81 73.9,49.81 74.03,49.93 74.03,50.15 v2(73.9,50.28)
  BOTTOM w0.099: U17.F3 V_A-DQS0-P.1
DDR0_32A_DQS1_N: length 14.5
  TOP w0.099: v2(70.9,47.28) U1.AC4
  03_SIG w0.096: V_A-DQS1-N.1 75.78,53.36 75.28,53.36 74.68,52.76 74.68,50.06 74.57,49.95 74.57,49.46 75.03,49 75.4,49 75.81,48.59 75.81,48.18 75.61,47.98 74.63,47.98 74.33,47.68 72.39,47.68 72.29,47.58 72.29,47.12 72.06,46.89 72.02,46.89 72.02,46.89 71.65,46.89 71.65,46.88 71.3,46.88 v2(70.9,47.28)
  BOTTOM w0.099: U17.B7 V_A-DQS1-N.1
DDR0_32A_DQS1_P: length 14.3
  TOP w0.099: v8(71.9,47.28) U1.AC3
  03_SIG w0.096: v8(71.9,47.28) 71.77,47.41 71.77,47.68 71.99,47.89 74.24,47.89 74.54,48.19 75.52,48.19 75.6,48.27 75.6,48.5 75.31,48.79 74.95,48.79 74.36,49.37 74.36,50.04 74.42,50.1 74.42,52.87 75.17,53.62 76.32,53.62 V_A-DQS1-P.1
  BOTTOM w0.099: U17.C7 V_A-DQS1-P.1
DDR0_32A_DQS2_N: length 13.3
  TOP w0.099: v8(70.9,44.28) U1.Y4
  04_SIG w0.096: V_A-DQS2-N.1 78.77,44.25 78.52,44 78.52,43.63 78.9,43.24 78.9,43.04 78.66,42.8 78.23,42.8 77.65,43.38 75.25,43.38 74.97,43.65 74.97,44.63 74.69,44.92 74.26,44.92 74.23,44.89 71.54,44.89 70.93,44.28 v8(70.9,44.28)
  BOTTOM w0.099: U18.G3 V_A-DQS2-N.1
DDR0_32A_DQS2_P: length 13
  TOP w0.099: v2(71.9,44.28) U1.Y3
  04_SIG w0.096: V_A-DQS2-P.1 79.14,44.04 78.93,44.04 78.78,43.89 78.78,43.74 79.17,43.35 79.17,42.93 78.77,42.54 78.12,42.54 77.54,43.12 75.14,43.12 74.71,43.54 74.71,44.52 74.58,44.65 74.26,44.65 74.23,44.68 71.64,44.68 71.56,44.6 71.56,44.4 71.68,44.28 v2(71.9,44.28)
  BOTTOM w0.099: U18.F3 V_A-DQS2-P.1
DDR0_32A_DQS3_N: length 10.6
  TOP w0.099: v8(72.9,43.28) U1.W2
  03_SIG w0.096: v8(72.9,43.28) 74.16,42.69 74.41,42.69 74.91,42.19 75.93,42.19 76.43,42.69 77.06,42.69 77.31,42.94 78.23,42.94 78.33,42.84 78.33,42.53 78.12,42.32 76.63,42.32 76.27,41.96 76.27,41.42 V_A-DQS3-N.1
  BOTTOM w0.099: U18.B7 V_A-DQS3-N.1
DDR0_32A_DQS3_P: length 10.5
  TOP w0.099: v2(73.9,43.28) U1.W1
  03_SIG w0.096: V_A-DQS3-P.1 76.94,41.3 76.71,41.3 76.61,41.4 76.61,41.93 76.74,42.06 78.23,42.06 78.59,42.43 78.59,42.94 78.33,43.2 77.2,43.2 76.95,42.95 76.33,42.95 75.83,42.45 75.02,42.45 74.52,42.95 74.23,42.95 v2(73.9,43.28)
  BOTTOM w0.099: U18.C7 V_A-DQS3-P.1
DDR0_32A_DQS4_N: length 19.6
  TOP w0.099: v2(73.9,39.28) U1.T1
  04_SIG w0.096: v2(73.9,39.28) 73.54,39.28 73.16,38.91 73.16,38.6 73.53,38.23 73.53,37.58 73.56,37.55 73.56,32.21 74.29,31.48 74.68,31.48 74.79,31.58 74.79,32.35 75.05,32.61 75.54,32.61 75.8,32.35 75.8,31.58 75.9,31.48 76.51,31.48 76.61,31.58 76.61,32.11 76.87,32.36 77.45,32.36 77.71,32.11 77.71,31.58 77.82,31.48 78.18,31.48 78.29,31.58 78.29,32.49 78.55,32.75 79.15,32.75 V_A-DQS4-N.1
  BOTTOM w0.099: U19.G3 V_A-DQS4-N.1
DDR0_32A_DQS4_P: length 19.5
  TOP w0.099: v8(72.9,39.28) U1.T2
  04_SIG w0.096: v8(72.9,39.28) 72.9,38.49 73.27,38.12 73.27,37.47 73.3,37.45 73.3,32.1 74.18,31.22 74.79,31.22 75.05,31.47 75.05,32.25 75.15,32.35 75.43,32.35 75.54,32.25 75.54,31.47 75.79,31.22 76.61,31.22 76.87,31.47 76.87,32 76.98,32.1 77.34,32.1 77.45,32 77.45,31.47 77.71,31.22 78.29,31.22 78.55,31.47 78.55,32.38 78.65,32.49 79.14,32.49 V_A-DQS4-P.1
  BOTTOM w0.099: U19.F3 V_A-DQS4-P.1
DDR0_32A_DRAMRST_L: length 61.4
  03_SIG w0.189: v8(70.9,37.28) 71.61,38 79.84,38 80.38,38.54 80.39,38.54 80.64,38.79 80.64,46.35 80.51,46.48 80.51,50.19 80.89,50.57 80.89,51.84 82.16,53.11 85,53.11 87.84,55.95 87.84,56.5 v3(87.41,56.93)
  BOTTOM w0.139: 87.91,45.86 v3(87.41,45.37) 87.91,44.87 ; 87.41,33.81 87.91,34.31 ; v3(87.41,56.93) 87.91,56.43
  BOTTOM w0.14: 87.91,34.31 88.01,34.41 88.01,44.78 87.91,44.87 ; 87.91,56.43 88.01,56.33 88.01,45.96 87.91,45.86
  BOTTOM w0.147: U18.T2 v3(87.41,45.37) ; U17.T2 v3(87.41,56.93) ; U19.T2 87.41,33.81
  BOTTOM w0.234: v8(70.9,37.28) 70.59,36.98 R272.2
DDR0_32A_ODT0: length 67.2
  TOP w0.147: R354.1 81.65,34.78 v3(81.81,34.61)
  TOP w0.234: v2(67.9,45.28) U1.AA7
  03_SIG w0.189: v2(67.9,45.28) 68.4,45.78 68.4,50.43 68.82,50.85 68.82,52.7 68.57,52.96 68.57,53 68.46,53.1 68.46,54.41 68.11,54.76 68.11,57.13 68.12,57.14 68.12,57.36 70.49,59.73 70.93,59.73 71.08,59.58 71.08,58.73 71.24,58.57 71.48,58.57 71.64,58.73 71.64,59.58 71.79,59.73 72.05,59.73 72.2,59.58 72.2,58.73 72.36,58.57 72.59,58.57 72.76,58.73 72.76,59.58 72.91,59.73 73.16,59.73 73.32,59.58 73.32,58.73 73.48,58.57 73.71,58.57 73.87,58.73 73.87,59.58 74.03,59.73 74.28,59.73 74.43,59.58 74.43,58.73 74.6,58.57 74.83,58.57 74.99,58.73 74.99,59.58 75.14,59.73 75.4,59.73 75.55,59.58 75.55,58.73 75.71,58.57 75.95,58.57 76.11,58.73 76.11,59.58 76.26,59.73 76.52,59.73 76.67,59.58 76.67,58.73 76.83,58.57 77.06,58.57 77.23,58.73 77.23,59.42 77.39,59.59 77.8,59.59 77.97,59.42 77.97,58.73 78.13,58.57 79.3,58.57 79.34,58.53 81.01,58.53 v3(81.81,57.73)
  07_SIG w0.121: v3(81.81,57.73) 82.21,57.33 82.21,46.56 v10(81.81,46.17) 82.21,45.77 82.21,35.01 v3(81.81,34.61)
  BOTTOM w0.147: U18.K1 v10(81.81,46.17) ; U17.K1 v3(81.81,57.73) ; U19.K1 v3(81.81,34.61)
DDR0_32A_RAS_L: length 67.5
  TOP w0.147: V3_A-RAS.1 81.81,32.61 R225.1
  TOP w0.234: v2(67.9,46.28) U1.AB7
  07_SIG w0.121: V1_A-RAS.1 81.81,55.69 81.42,55.29 81.42,44.96 V2_A-RAS.1 81.42,44.17 81.42,33.41 V3_A-RAS.1
  07_SIG w0.189: v2(67.9,46.28) 68.44,45.74 72.07,45.74 72.38,46.05 72.38,58.67 72.54,58.84 74.14,58.84 74.33,58.65 74.33,55.47 74.34,55.47 74.34,55.1 74.33,55.09 74.33,54.46 74.47,54.32 74.8,54.32 74.98,54.5 74.98,58.61 75.21,58.84 76.69,58.84 76.86,58.67 76.86,58.36 77.03,58.19 77.26,58.19 77.43,58.36 77.43,58.67 77.6,58.84 77.91,58.84 78.08,58.67 78.08,58.36 78.25,58.19 78.48,58.19 78.65,58.36 78.65,58.67 78.82,58.84 79.22,58.84 79.38,58.67 79.38,58.48 79.55,58.32 79.79,58.32 79.95,58.48 79.95,58.67 80.12,58.84 80.52,58.84 80.76,58.6 80.76,56.3 80.94,56.13 V1_A-RAS.1
  BOTTOM w0.147: U17.J3 V1_A-RAS.1 ; U18.J3 V2_A-RAS.1 ; U19.J3 V3_A-RAS.1
DDR0_32A_VREF: length 5.9
  TOP w0.254: v2(64.9,42.28) U1.V10 ; v2(64.9,43.28) U1.W10
  BOTTOM w0.254: v1(67.68,43.28) 66.46,43.78 R284.1 R283.2 v2(64.9,43.28) C196.1 v2(64.9,42.28)
DDR0_32A_VREF0B: length 13.3
  TOP w0.254: C206.1 80.8,54.67 81.52,55.4 82.28,55.4 82.58,55.1 R289.2 83.68,54.63 83.93,54.38 v1(83.93,53.87) 84.21,53.59 v3(84.21,51.33) ; C206.1 80.38,55.4 80.76,55.78 80.76,57.18 v3(80.21,57.73) ; C206.1 80.34,54.63 R288.1
  BOTTOM w0.254: U17.M8 v3(84.21,51.33) ; U17.H1 v3(80.21,57.73)
DDR0_32A_VREF1B: length 47.9
  TOP w0.254: R363.2 79.02,35.8 R364.1 79.74,35.33 79.87,35.2 79.87,34.95 v3(80.21,34.61) 80.88,34.61 C264.1 81.01,34.95 80.76,35.2 80.76,37.74 81.01,38 81.01,41.04 81.65,41.68 v1(82.54,41.68) 83.81,41.68 84.21,41.27 ; C263.1 80.76,46.71 v3(80.21,46.17) ; C263.1 80.07,47.48 79.87,47.69 R361.2 R362.1 ; C263.1 81.61,47.48 81.78,47.65 87.74,47.65 88.38,47.01 88.38,42.31 87.74,41.68 84.62,41.68 84.21,41.27 ; 84.21,41.27 v3(84.21,39.77)
  08_SIG w0.203: v3(84.21,28.21) 84.21,30.86 83.55,31.52 81.78,31.52 81.01,32.28 81.01,33.81 v3(80.21,34.61)
  BOTTOM w0.254: U18.H1 v3(80.21,46.17) ; U19.M8 v3(84.21,28.21) ; U19.H1 v3(80.21,34.61) ; U18.M8 v3(84.21,39.77)
DDR0_32A_WE_L: length 67.1
  TOP w0.147: R227.1 83.41,32.43 V3_A-WE.1
  TOP w0.234: v8(68.9,47.28) U1.AC6
  04_SIG w0.121: V1_A-WE.1 83.02,55.73 83.02,44.96 V2_A-WE.1 83.02,44.17 83.02,33.41 V3_A-WE.1
  07_SIG w0.121: V1_A-WE.1 83.41,56.37 83.81,56.76 83.81,57.43
  07_SIG w0.189: 83.81,57.43 83.81,57.53 83.78,57.55 83.78,57.9 83.81,57.93 83.81,59.04 83.61,59.23 83.4,59.23 83.22,59.05 83.22,57.58 83.1,57.45 82.79,57.45 82.59,57.66 82.59,59.08 82.44,59.23 69.38,59.23 69.23,59.08 69.23,58.83 69.41,58.65 71.82,58.65 71.95,58.52 71.95,58.11 71.74,57.91 70.65,57.91 70.52,57.78 70.52,57.3 70.7,57.12 71.18,57.12 71.36,56.95 71.36,47.06 71.06,46.76 69.42,46.76 v8(68.9,47.28)
  BOTTOM w0.147: U18.L3 V2_A-WE.1 ; U17.L3 V1_A-WE.1 ; U19.L3 V3_A-WE.1
DDR_1.8V: length 8.6
  TOP w0.203: 20.82,20.41 U9.11
  TOP w0.508: 23.98,15.9 L12.2 24.12,15.9 TP44.1 ; 22.27,20.41 20.82,20.41
  BOTTOM w0.508: L7.1 v2(56.9,36.28)
  vias: v4(24.37,17.93) v5(22.47,19.96) v5(24.37,19.2)
DDR_VDDQ: length 92.2
  TOP w0.203: U3.2 82.52,17.7 v5(82.28,17.93) ; R335.2 83.72,24.15 v5(83.68,24.15)
  TOP w0.254: C265.1 76.28,46.23 v3(76.21,46.17) ; v2(69.9,36.28) U1.N5 ; R288.2 78.35,54.63 v5(77.97,55.04) ; C211.1 84.7,49.43 85.01,49.74 v3(85.01,50.53) ; C213.1 80.22,50.53 v3(80.21,50.53) ; v2(70.9,28.28) U1.E4 ; v3(77.81,27.41) 77.8,27.4 C219.1 ; v3(78.61,34.61) 78.18,35.04 R364.2 ; v5(78.22,12.34) 78.22,12.6 77.97,12.85 77.97,14.45 TP54.1 ; C108.1 84.99,35.48 v3(85.01,35.46) ; C111.1 80.53,26.67 80.21,26.99 v3(80.21,27.41) ; v2(70.9,25.28) U1.B4 ; C215.1 84.7,38.25 85.01,38.57 v3(85.01,38.97) ; v2(72.9,36.28) U1.N2 ; v2(66.9,25.28) U1.B8 ; v3(85.01,46.17) 85.01,46.7 84.7,47.01 C216.1 ; v2(68.9,41.28) U1.U6 ; v2(71.9,32.28) U1.J3 ; v2(64.9,31.28) U1.H10 ; C266.1 77.8,38.96 v3(77.81,38.97) ; C217.1 76.15,34.68 v3(76.21,34.61) ; v2(68.9,25.28) U1.B6 ; v2(65.9,49.28) U1.AE9 ; v2(72.9,52.28) U1.AH2 ; C212.1 77.8,50.51 v3(77.81,50.53) ; R340.2 76.98,33.84 v3(77.01,33.81) ; R362.2 78.6,46.18 v3(78.61,46.17) ; v3(79.41,29.01) 79.19,29.23 79.08,29.23 78.48,29.83 C105.2 77.08,29.83 76.82,30.08 76.82,31.86 R338.2 ; v2(64.9,39.28) U1.T10 ; v2(66.9,28.28) U1.E8 ; U1.C9 v2(65.9,26.28) ; v3(79.41,52.13) 79.53,52.24 C214.1 ; v2(66.9,45.28) U1.AA8 ; v3(85.01,27.41) 85.01,26.67 C218.1 ; v2(66.9,36.28) U1.N8 ; v2(71.9,41.28) U1.U3 ; v2(72.9,45.28) U1.AA2 ; v2(69.9,45.28) U1.AA5 ; v2(68.9,32.28) U1.J6
  TOP w0.483: v2(72.9,25.28) U1.B2
  04_SIG w0.254: v5(82.28,17.93) 83.68,19.33 v5(83.68,24.15)
  BOTTOM w0.203: v2(66.9,36.28) R310.2
  BOTTOM w0.254: C194.1 v2(66.9,45.28) U1.AA8 R284.2 ; U17.D9 v3(77.01,50.53) ; U17.H2 v3(80.21,56.93) ; U1.AA2 v2(72.9,45.28) ; U18.D2 v3(77.01,45.37) ; C1.1 64.69,39.49 v2(64.9,39.28) ; U17.R1 v3(86.61,57.73) ; U19.K8 v3(82.61,28.21) ; v2(65.9,49.28) C195.1 ; U19.E9 v3(77.81,27.41) ; U18.A8 v3(75.41,39.77) ; U17.N1 v3(85.01,57.73) ; U19.D2 v3(77.01,33.81) ; U19.R9 v3(86.67,27.35) ; U17.C1 v3(76.21,57.73) ; U18.N1 v3(85.01,46.17) ; U17.E9 v3(77.81,50.53) ; U19.N9 v3(85.01,27.41) ; U17.B2 v3(75.41,56.93) U17.A1 ; U19.K2 v3(82.61,33.81) ; U18.H2 v3(80.21,45.37) ; U18.C1 v3(76.21,46.17) ; U18.K2 v3(82.61,45.37) ; U18.R9 v3(86.61,38.97) ; U17.C9 v3(76.21,50.53) ; U17.K8 v3(82.61,51.33) ; v2(68.9,41.28) C190.1 ; U18.K8 v3(82.61,39.77) ; U18.G7 v3(79.41,40.57) ; U18.F1 v3(78.61,46.17) ; U18.R1 v3(86.61,46.17) ; U18.H9 v3(80.21,38.97) ; U19.R1 v3(86.61,34.67) ; U18.D9 v3(77.01,38.97) ; v2(71.9,41.28) U1.U3 ; U19.C1 v3(76.21,34.61) ; v2(72.9,52.28) U1.AH2 R146.2 ; U17.N9 v3(85.01,50.53) ; U19.H2 v3(80.21,33.81) ; U17.R9 v3(86.61,50.53) ; U18.A1 v3(75.41,45.37) U18.B2 ; U17.F1 v3(78.61,57.73) ; U19.G7 v3(79.41,29.01) ; U17.A8 v3(75.41,51.33) ; U17.D2 v3(77.01,56.93) ; U17.K2 v3(82.61,56.93) ; C193.1 v2(69.9,45.28) ; U18.C9 v3(76.21,38.97) ; U19.A8 v3(75.41,28.21) ; U17.H9 v3(80.21,50.53) ; U19.H9 v3(80.21,27.41) ; U19.C9 v3(76.21,27.41) ; U17.G7 v3(79.41,52.13) ; U19.B2 v3(75.41,33.81) U19.A1 ; U19.F1 v3(78.61,34.61) ; U18.E9 v3(77.81,38.97) ; U18.N9 v3(85.01,38.97) ; v3(85.01,35.46) 84.61,35.06 U19.N1 ; U19.D9 v3(77.01,27.41)
  BOTTOM w0.508: v2(66.9,28.28) 66.9,27.19 C68.1 ; C67.1 68.39,31.24 68.9,31.75 v2(68.9,32.28)
  vias: v3(76.72,36.78) v4(79.11,12.72) v4(79.11,11.2) v4(79.62,9.29) v5(79.87,8.02) v5(79.87,7.14) v5(80.89,8.02) v5(80.89,7.14)
DDR_VTT: length 3.5
  TOP w0.203: v5(82.28,16.91) 82.66,17.3 U3.3
  BOTTOM w0.254: C138.1 81.9,16.72 ; C139.1 80.51,16.72 ; C140.1 79.24,16.72
  vias: v1(78.98,17.3) v5(80.12,17.17) v5(81.39,17.17) v5(89.65,19.58) v5(89.65,17.3) v7(89.65,18.44) v7(89.65,16.15)
DEBUG_CPLD_PGRM_JTAG_TCK: length 38.3
  TOP w0.147: v4(27.55,29.07) 27.02,28.54 U12.2
  04_SIG w0.121: v4(23.48,12.91) 23.93,13.36 23.93,13.61 24.57,14.24 24.93,14.24 25.69,13.49 29.96,13.49 30.58,12.86 33.4,12.86 34.15,13.61 34.66,13.61 35.04,13.23 36.06,13.23 v4(36.44,13.61)
  08_SIG w0.121: v4(23.48,12.91) 23.48,13.23 25.78,15.53 25.78,19.47 26.4,20.09 26.4,23.34 26.46,23.4 26.46,24.47 25.64,25.3 25.64,27.2 27.51,29.07 v4(27.55,29.07)
  BOTTOM w0.147: v4(23.48,12.91) 23.16,12.91 22.21,13.87 J5.15
DEBUG_CPLD_PGRM_JTAG_TDI: length 40.1
  TOP w0.147: U12.5 25.51,27.13 25.51,27.84 25.11,28.24 24.6,28.24 24.12,28.73 v4(24.12,29.04) R71.2
  04_SIG w0.121: v4(38.34,13.61) 37.33,13.61 36.07,12.36 29.7,12.36 29.59,12.47 28.75,12.47 28.74,12.47 25.19,12.47 v5(24.75,12.91)
  08_SIG w0.121: v5(24.75,12.91) 24.18,12.91 23.98,12.72 23.98,12.71 23.69,12.41 23.27,12.41 22.98,12.71 22.98,13.44 25.28,15.74 25.28,19.68 25.58,19.98 25.58,24.6 24.37,25.8 24.37,28.79 v4(24.12,29.04)
  BOTTOM w0.147: J5.17 23.48,13.74 24.31,12.91 v5(24.75,12.91)
DEBUG_CPLD_PGRM_JTAG_TDO: length 32.3
  TOP w0.147: U12.11 25.02,23.67 R70.2
  07_SIG w0.121: v4(25.13,23.58) 25.13,22.38 25.26,22.25 25.26,17.93 24.37,17.04 24.37,14.18 v4(24.75,13.8) 25.52,14.57 25.52,15.37 27.96,17.8 29.04,17.8 29.22,17.99 30.43,17.99 30.69,17.73 30.69,17.27 32.53,15.43 32.9,15.43 33.16,15.69 33.16,15.79 34.08,16.72 36.83,16.72 38.38,15.17 38.53,15.17 39.71,13.99 v4(40.25,13.99)
DEBUG_CPLD_PGRM_JTAG_TMS: length 34.4
  TOP w0.147: U12.14 26.52,24.41 26.8,24.13 27.23,24.13 R69.2
  07_SIG w0.121: v4(26.02,14.06) 26.02,15.16 27.55,16.69 30.57,16.69 32.32,14.93 33.03,14.93 33.46,15.36 34.15,15.36 34.38,15.59 34.43,15.59 34.83,15.99 36.06,15.99 36.22,15.84 37,15.84 38.21,14.63 38.66,14.63 39.74,13.55 40.43,13.55 41.26,14.39 v5(41.26,15.39)
  08_SIG w0.121: v4(27.8,23.47) 27.8,22.5 26.91,21.61 26.91,19.07 26.28,18.45 26.28,14.32 v4(26.02,14.06)
  BOTTOM w0.147: v5(41.26,15.39) 41.26,14.88 TP11.1
EXT_3.3V: length 106.9
  TOP w0.127: 38.17,29.97 38.37,29.77 v3(38.37,28.98) ; U2.P14 30.95,37.23 v3(30.95,37.72) ; v3(35.8,32.71) 36.09,32.71 36.59,32.21 36.59,32.14 36.91,31.83 U2.D3 ; U2.P1 38.21,37.08 38.21,37.11 v3(38.62,37.51) ; v3(35.32,31.93) 35.32,31.82 35.73,31.41 35.73,31.4 35.85,31.28 U2.C5 ; U2.L1 38.52,35.89 v3(39.41,35.89)
  TOP w0.147: U2.A1 37.91,30.22 38.17,29.97 ; U2.D14 30.65,31.78 v3(30.09,31.24) ; U2.L12 32.96,35.28 v3(33.03,35.18)
  TOP w0.203: U12.16 28.18,25.68 28.63,25.23 v4(28.63,24.66) ; v5(21.7,55.52) 21.2,56.03 21.2,57.55 20.9,57.85 R73.1 R396.1 ; R131.2 v7(5.58,25.8) ; R62.1 23.9,22.17 24.54,22.17 25.09,22.72 R70.1 R61.1 26.07,22.72 26.58,22.21 27.29,22.21 R69.1 27.97,22.88 R86.2 R87.2 ; U14.19 v5(33.15,51.72) 32.52,52.35 31.95,52.35 31.8,52.2 31.79,52.2 31.66,52.06 31.66,52.06 R15.1 ; v4(38.68,53.62) 38.29,53.22 U14.9 ; v5(49.64,11.07) 49.94,10.78 U4.8 ; R130.2 v5(6.46,25.8) ; v5(18.55,32.83) 19.15,33.42 20.31,33.42 20.9,34.02 R395.1 ; R278.2 v4(47.36,6.59) ; R14.1 38.81,56.96 39.17,56.6 39.17,55.25 39.03,55.11 39.03,55.1 C24.1 ; R100.2 v5(4.69,25.8)
  TOP w0.254: U20.16 22.94,55.14 C284.1 21.82,55.41 v5(21.7,55.52) ; R87.2 28.7,24.59 v4(28.63,24.66) ; R85.2 28.7,22.05 R86.2
  TOP w0.508: v5(4.91,54.91) 4.91,55.88 6.34,57.3 7.99,57.3 8.95,56.34 DS1.1 ; v4(38.68,53.62) C24.1
  02_GND w0.121: 33.41,30.73 v3(31.76,29.08)
  02_GND w0.127: U2.B10 33.41,30.73 ; U2.N11 32.91,35.33 v3(33.03,35.18)
  BOTTOM w0.203: v3(35.8,32.71) 35.85,32.66 R48.1 ; R53.1 32.12,36.18 R52.1 ; v4(3.77,40.96) 4.55,40.96 4.56,40.94 5.07,40.94 5.08,40.96 R377.2 ; R379.2 26.31,54.13 26.61,54.13 26.69,54.2 26.7,54.2 R369.2 ; R378.2 v4(3.82,49.39)
  BOTTOM w0.254: v4(13.32,12.91) 13.39,12.98 13.83,12.98 14.59,13.74 J5.3 ; U21.16 8.28,45.36 C285.1 10.27,45.58 10.32,45.53 v5(10.93,45.53) ; v3(30.95,37.72) 30.95,39.46 C120.1 ; C121.1 38.05,29.3 v3(38.37,28.98) ; J4.154 v5(18.55,31.56) ; v3(31.76,29.08) 31.9,28.94 C118.1 ; R380.2 R370.2 ; R380.2 25.51,54.46 25.74,54.23 25.74,54.19 R379.2 ; R380.2 R399.1 21.92,55.74 v5(21.7,55.52) ; v3(35.32,31.93) 35.32,31.63 34.82,31.14 C122.1 ; J4.146 v5(18.55,32.83) ; v3(33.03,35.18) 33.01,35.23 R52.1 ; R377.2 v1(5.83,39.77) ; v4(3.77,40.96) 3.82,39.8 v1(3.8,39.77) ; C119.1 39.47,37.98 39,37.51 v3(38.62,37.51) 38.24,37.51 37.71,36.98 R397.1 R398.1 37.58,36.09 37.83,35.84 37.83,35.25 R50.1
  BOTTOM w0.305: v4(28.63,24.66) 28.12,24.15 28.1,24.15 27.95,24 27.25,24 27.13,24.12 27.08,24.12 26.66,24.53 22.59,24.53 22.09,25.04 22.09,28.89 v4(21.74,29.36)
  BOTTOM w0.508: 33.17,51.75 33.17,52.51 33.48,52.82 C36.1 ; 33.17,51.75 v5(33.15,51.72) ; 33.17,51.75 C84.1 ; C123.1 27.97,25.77 28.63,25.11 v4(28.63,24.66)
  vias: v4(24.12,29.93) v4(29.83,9.87) v4(67.93,12.71) v4(84.57,21.32)
EXT_3.3V_PGOOD: length 42.3
  TOP w0.127: v3(36.19,32.01) 36.2,32.01 36.31,31.9 36.31,31.85 36.6,31.56 36.63,31.56 U2.C3
  TOP w0.147: R102.2 52.67,10.13 U4.7 49.97,10.13 v7(49.64,9.8) ; R102.2 R121.2 ; R102.2 52.78,10.15 53.2,10.56 53.2,11.58 TP63.1
  03_SIG w0.121: v2(44.9,31.28) 44.5,30.88 42.54,30.88 42.28,31.14 42.28,31.77 41.47,32.58 41.47,32.59 41.21,32.85 41.2,32.85 40.5,33.55 37.73,33.55 v3(36.19,32.01)
  08_SIG w0.121: v2(44.9,31.28) 45.33,30.88 45.33,23.14 45.83,22.63 45.83,19.96 46.6,19.2 46.6,15.64 49.14,13.1 49.14,10.31 v7(49.64,9.8)
EXT_3.3V_THRESHOLD: length 6.5
  TOP w0.147: R267.1 R316.2 C249.1 49.56,7.43 49.77,7.64 50.66,7.64 v7(51.17,8.15) U4.5 52.23,8.83 R121.1
EXT_12.0V: length 13.4
  TOP w0.203: U13.11 v5(66.41,11.09)
  TOP w0.254: v7(47.23,5.48) 47.03,5.69 R279.2
  TOP w0.508: v5(7.1,28.85) 8.24,28.85 8.5,29.11 C242.1 8.46,30.12 v5(7.1,30.12) ; v5(26.66,12.98) 25.9,12.98 25.39,13.49 25.39,14.41 R312.1 ; v5(44.44,20.09) 44.16,19.81 R402.1
  BOTTOM w0.254: J4.153 v5(19.82,31.56) ; J4.145 v5(19.82,32.83)
  vias: v4(40.88,16.37) v4(56.46,19.86) v4(57.48,19.86) v5(53.45,22.12) v5(54.85,21) v5(56.6,22.63) v5(56.59,21.11) v5(57.86,22.63) v5(57.86,21.11) v5(64.88,6.63) v5(66.15,6.63) v5(66.66,5.36) v5(66.66,4.09) v5(74.03,22.12) v5(74.03,21.11) v5(75.04,22.12) v5(75.04,21.11) v5(76.19,22.38) v5(76.19,21.11) v5(77.46,22.38) v5(77.46,21.11) v5(84.57,8.53) v5(84.57,7.26) v5(85.84,8.53) v5(88.38,7.26) v5(89.65,7.26) v9(51.89,20.06) v9(53.26,19.2) v9(71.49,20.06) v9(72.86,19.2)
EXT_12.0V_PGOOD: length 35.3
  TOP w0.127: U2.C1 38.13,31.05 38.99,31.05 v3(39.41,31.47)
  TOP w0.147: TP62.1 44.14,9.04 R122.2 R101.2 45.07,10.78 U4.1 48.08,10.78 v5(48.37,11.07)
  03_SIG w0.121: v2(44.9,30.25) 41.9,30.25 41.39,30.76 40.12,30.76 v3(39.41,31.47)
  08_SIG w0.121: v2(44.9,30.25) 45.1,30.05 45.1,23.67 45.08,23.64 45.08,23.04 45.33,22.79 45.33,20.21 45.01,19.89 45.01,19.53 45.33,19.21 45.33,19.2 46.22,18.31 46.22,15.39 48.76,12.85 48.76,11.45 v5(48.37,11.07)
EXT_12.0V_THRESHOLD: length 6.8
  TOP w0.147: U4.3 45.52,9.48 R122.1 45.07,8.66 v7(45.58,8.15) R317.2 ; R279.1 45.49,5.83 45.07,6.25 45.07,6.92 R317.2 ; R317.2 C248.1
GH_PHASE1: length 21.3
  07_SIG w0.121: v5(71.72,22.12) 71.72,21.21 71.13,20.62 70.27,20.62 69.98,20.33 69.98,20.31 69.3,19.64 68.9,19.64 68.66,19.88 66.58,19.88 65.65,18.95 61.58,18.95 61.07,18.44 61.07,13.61 60.31,12.85 v4(60.31,11.58)
  BOTTOM w0.147: v5(71.72,22.12) 71.23,21.64 U6.6
GH_PHASE2: length 13.1
  07_SIG w0.121: v5(52.02,22.12) 50.52,20.62 48.02,20.62 46.6,19.2 45.2,19.2 44.95,19.45 42.91,19.45 42.41,18.95 v4(41.77,18.95)
  BOTTOM w0.147: v5(52.02,22.12) 51.76,22.12 51.63,21.99 U5.6
GL_PHASE1: length 13
  07_SIG w0.121: v4(61.84,11.58) 62.6,10.82 65.14,10.82 65.83,11.51 65.83,17.16 v5(67.11,18.43)
  BOTTOM w0.147: U6.36 v5(67.11,18.43)
GL_PHASE2: length 5.4
  07_SIG w0.121: v4(43.29,18.95) 47,18.95 v5(47.51,18.43)
  BOTTOM w0.147: U5.36 v5(47.51,18.43)
HOST_RESET_REQ_L: length 49.6
  TOP w0.127: v3(39.41,33.98) 38.99,33.56 38.12,33.56 U2.H1
  TOP w0.147: TP18.1 25.64,11.07 24.89,10.32 22.41,10.32 v4(22.21,10.12)
  03_SIG w0.121: v3(39.41,33.98) 39.41,34.01 39.04,34.38 37.01,34.38 36.56,33.93 35.67,33.93 35.66,33.94 34.9,33.94 34.85,33.99 34.52,33.99 34.47,33.94 32.51,33.94 30.72,32.15 29.58,32.15 27.8,30.38 27.17,30.38 26.15,31.39 v5(25.26,31.39)
  08_SIG w0.121: v5(25.26,31.39) 24.37,30.5 23.86,30.5 23.23,29.87 23.23,27.2 23.48,26.95 23.48,24.22 23.8,23.9 23.8,23.4 24.06,23.14 24.43,23.14 24.69,22.88 24.69,22.06 24.12,21.49 24.12,20.34 22.72,18.95 22.72,17.55 21.58,16.41 21.58,12.34 22.21,11.71 v4(22.21,10.12)
  BOTTOM w0.127: v3(39.41,33.98) 38.99,33.56 38.1,33.56 37.74,33.21 R48.2
L_1_CORE_PHASE: length 10.4
  TOP w0.203: R171.1 69.08,21.4 69.08,21.11 68.44,20.47 68.44,17.55 68.69,17.3 72.73,17.3 L17.1
  BOTTOM w0.203: v9(72.86,18.06) 73.24,18.43 U6.15
  vias: v1(67.68,13.99) v9(69.1,18.06) v9(69.1,16.41) v9(70.35,18.06) v9(70.35,16.41) v9(71.62,18.06) v9(71.62,16.41) v9(72.86,16.41)
L_2_CORE_PHASE: length 10
  TOP w0.203: R168.1 55.4,17.59 55.11,17.3 51.07,17.3 L18.1
  BOTTOM w0.203: v9(53.26,18.06) 53.64,18.43 U5.15
  vias: v1(46.85,15.01) v9(49.5,18.06) v9(49.5,16.41) v9(50.75,18.06) v9(50.75,16.41) v9(52.02,18.06) v9(52.02,16.41) v9(53.26,16.41)
MAIN_3.3V: length 7.1
  BOTTOM w0.254: J4.156 v5(16.01,31.56) ; v6(17.28,31.56) J4.155 17.92,27.05 TP68.1 ; J4.147 v5(17.28,32.83)
MH_1: length 1.2
  TOP w0.508: 76.19,11.83 77.04,12.69 R152.1
  vias: v5(70.09,8.02) v5(73.77,4.09) v5(77.58,8.15) v7(73.77,11.5)
MH_2: length 1.4
  BOTTOM w0.508: R149.2 32.12,43.08
  vias: v5(32.5,44.09) v5(36.31,40.16) v5(40.12,44.09) v7(36.31,47.9)
MUX_NFP_GPIO0_NWK0_I2C_SCL: length 55.8
  TOP w0.132: U1.Y28 v2(45.9,44.28)
  03_SIG w0.121: v4(7.1,42.7) 7.1,41.93 7.99,41.04 10.15,41.04 10.53,41.43 10.53,41.81 10.59,41.87 10.59,41.9 10.85,42.16 12.91,42.16 13.3,42.55 14.54,42.55 15.57,41.51 15.57,40.06 15.99,39.65 16.5,39.65 17.13,39.01 17.39,39.01 18.06,38.34 18.23,38.34 18.25,38.35 18.74,38.35 19,38.09 19,37.76 19.65,37.11 19.98,37.11 20.49,36.6 24.37,36.6 24.54,36.77 25.89,36.77 25.92,36.8 26.64,36.8 26.67,36.77 27.15,36.77 27.37,36.98 27.8,36.98 30.59,39.77 32.37,39.77 33.01,40.41 35.67,40.41 35.86,40.6 38.27,40.6 41.56,43.88 42.07,43.88 42.3,44.12 42.3,44.24 42.5,44.44 42.5,44.45 42.73,44.69 42.74,44.69 42.79,44.73 44.02,44.73 44.3,44.45 44.3,44.31 44.73,43.88 45.5,43.88 v2(45.9,44.28)
  07_SIG w0.121: v4(7.1,42.7) 4.94,40.54 4.94,39.14 v7(4.43,38.63)
  BOTTOM w0.147: U21.3 6.46,43.9 6.46,43.33 6.59,43.2 6.85,43.2 6.95,43.1 R385.2
MUX_NFP_GPIO1_NWK0_I2C_SDA: length 55.4
  TOP w0.132: U1.W28 v2(45.9,43.28)
  03_SIG w0.121: v2(45.9,43.28) 45.9,43.27 45.45,42.82 44.69,42.82 44.44,43.08 44.44,43.46 44.18,43.71 42.66,43.71 42.3,43.36 42.3,43.12 42.07,42.88 41.32,42.88 37.96,39.52 32.56,39.52 32.44,39.39 31.1,39.39 29.93,38.22 29.92,38.22 29.69,37.99 29.58,37.99 28.56,36.98 28.51,36.98 28.05,36.52 25.69,36.52 25.26,36.09 20.16,36.09 20.08,36.17 19.67,36.17 19.38,36.46 19.38,37.02 19.05,37.36 17.13,37.36 16.62,37.87 16.62,38.12 16.37,38.38 14.59,38.38 14.3,38.67 14.3,41.52 13.66,42.16 13.29,42.16 13.03,41.9 13.03,41.52 12.69,41.17 12.05,41.17 11.54,40.66 11.54,40.16 11.29,39.9 7.76,39.9 v4(4.97,42.7)
  BOTTOM w0.147: v1(4.81,41.55) 4.97,41.71 v4(4.97,42.7) 4.95,42.71 U21.6
MUX_NFP_GPIO2_NWK1_I2C_SCL: length 54.3
  TOP w0.132: U1.Y29 v8(44.9,44.28)
  03_SIG w0.121: v8(44.9,44.28) 44.9,44.39 44.44,44.85 44.33,44.85 44.07,45.11 43.68,45.11 43.1,45.69 42.73,45.69 42.5,45.45 42.5,45.31 41.87,44.69 41.47,44.69 37.71,40.92 30.48,40.92 27.23,37.67 27.23,37.56 26.72,37.05 24.43,37.05 24.24,36.85 20.58,36.85 19.97,37.47 19.64,37.47 19.38,37.73 19.38,38.29 18.93,38.74 18.37,38.74 16.46,40.65 16.46,41.9 16.2,42.16 15.64,42.16 14.37,43.43 13.04,43.43 12.65,43.04 12.65,42.81 12.39,42.55 8.88,42.55 7.58,43.84 6.59,43.84 5.7,44.73 5.7,45.74 4.97,46.48 v4(4.97,47.65)
  BOTTOM w0.147: v4(4.97,47.65) 4.97,47.2 4.45,46.69 U21.10
MUX_NFP_GPIO3_NWK1_I2C_SDA: length 57.5
  TOP w0.132: U1.W29 v8(44.9,43.28)
  03_SIG w0.105: 45.4,45.04 45.76,44.68 46.06,44.68 46.29,44.45 46.29,44.12 46.06,43.89 45.93,43.89 45.59,43.55
  03_SIG w0.121: 45.59,43.55 45.33,43.28 v8(44.9,43.28) ; v4(7.1,47.65) 7.1,46.86 8.87,45.09 14.87,45.09 15.26,44.7 16.2,44.7 16.84,44.05 16.84,42.81 17.1,42.55 17.54,42.55 17.77,42.31 17.77,41.37 19.67,39.47 19.67,39.39 20.59,38.47 20.59,37.7 20.89,37.41 22.26,37.41 25.26,40.41 25.26,40.66 27.42,42.82 28.56,42.82 29.83,44.09 29.83,44.85 30.34,45.36 31.74,45.36 34.72,48.34 40.95,48.34 41.52,47.78 42.98,47.78 43.3,47.45 43.3,47.3 43.91,46.69 44.07,46.69 44.3,46.45 44.3,46.3 44.91,45.69 45.07,45.69 45.33,45.43 45.33,45.11 45.4,45.04
  BOTTOM w0.147: R388.2 6.85,47.55 6.85,47.27 6.59,47.01 6.21,47.01 5.95,46.76 U21.13
